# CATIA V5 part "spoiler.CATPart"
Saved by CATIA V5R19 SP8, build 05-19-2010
Part number: spoiler
Material "Carbone"
Bounding box of the stored display mesh (mm): x -500 to 500, y -109.216 to 90.265, z 0 to 38.35
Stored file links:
  G:\EU_thinkMotion\CFAO_2010\MMS_groupe1\MMS_groupe1\A reprendre\gduval\CFAO kinematic ok\spoiler.CATPart
  C:\Users\rcousturie\Desktop\CATMaterial1.CATMaterial
  C:\Users\rcousturie\Downloads\fibre-de-carbone.jpg
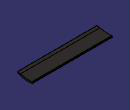
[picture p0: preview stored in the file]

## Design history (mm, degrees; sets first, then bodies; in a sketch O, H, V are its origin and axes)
Body1 (main body), material "Carbone"
  Sketch1 on yz-plane, origin (0, 0, 0), H (0, 1, 0), V (0, 0, 1)
    line L1 (18.5401, 0) -> (36.6287, 0)
    point P1 (-50, 0)
    point P2 (50, 0)
    line L2 (63.2694, 1.6473) -> (79.3205, 3.6399)
    point P3 (90.2771, 5)
    line L3 (85.4184, 20) -> (73.3297, 20)
    point P4 (0.5505, 20)
    line L4 (-71.2324, 32.0003) -> (-109.2165, 38.3503)
    line L5 (-109.2165, 38.3503) -> (-107.5293, 37.2576)
    arc A1 centre (36.6287, 216.2489) radius 216.2489 from (36.6287, 0) to (63.2694, 1.6473) ccw
    arc A2 centre (77.7811, 16.0406) radius 12.496 from (79.3205, 3.6399) to (90.2648, 15.4867) ccw
    arc A3 centre (85.4184, 15.1414) radius 4.8586 from (85.4184, 20) to (90.2648, 15.4867) cw
    arc A4 centre (73.3297, 896.7372) radius 876.7372 from (-71.2324, 32.0003) to (73.3297, 20) ccw
    arc A5 centre (18.5401, 231.9209) radius 231.9209 from (-107.5293, 37.2576) to (18.5401, 0) ccw
    distance P2 V = 50
    distance P3 H = 5
    distance P4 H = 20
    distance P1 P2 = 100
    radius A1 = 216.2489
    radius A2 = 12.496
    radius A3 = 4.8586
    radius A4 = 876.7372
    radius A5 = 231.9209
    horizontal: L1 H, L3 H
    coincidence: L4 P3, L1 P2, L2 P2, L2 P3, L4 P4, L3 P4, L5 P1, L1 P1
    tangency: A1 L1, A1 L2, A2 L2, A3 L3, A4 L4, A4 L3, A5 L5, A5 L1
  Pad1: profile Sketch1, direction (1, 0, 0), length 500, mirrored extent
